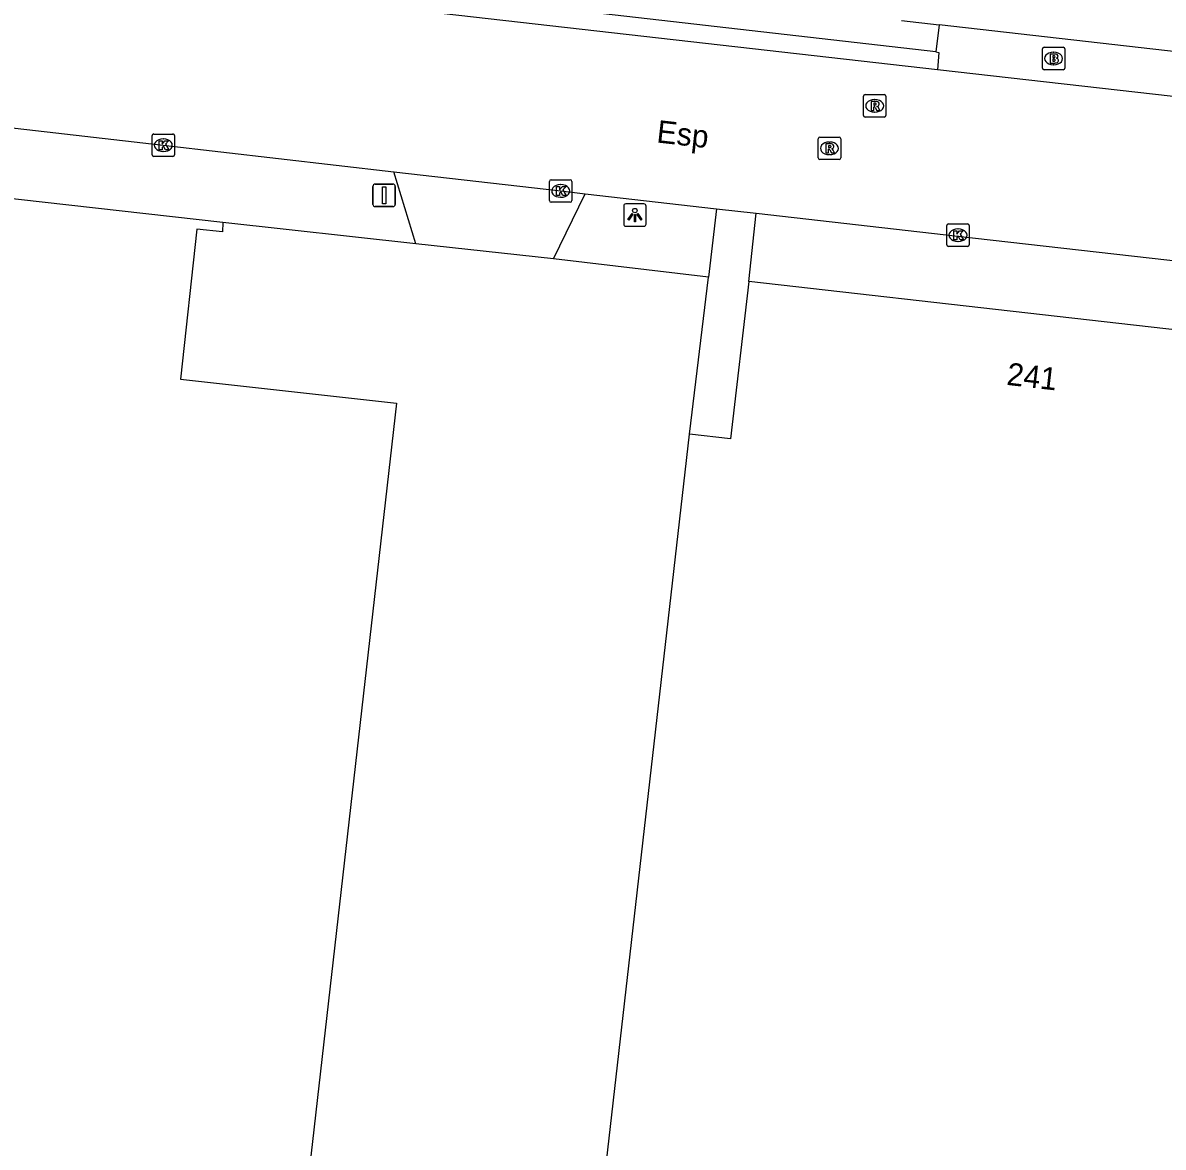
# Model space of a CAD drawing. Extents: x 161389 to 162585, y 388479 to 389761.
# Drawn here: x 162382.4 to 162433.2, y 388747.2 to 388797.2 of the extents above; entities that cross this region are included whole.
import ezdxf

# ---------------------------------------------------------------- set-up
doc = ezdxf.new("R2010")
doc.units = 0
for name, color, linetype in [('IMGEO_Afsluitpaal', 7, 'Continuous'), ('IMGEO_Brandkraan', 7, 'Continuous'), ('IMGEO_Groenvoorziening', 7, 'Continuous'), ('IMGEO_Haag', 7, 'Continuous'), ('IMGEO_Kolk', 7, 'Continuous'), ('IMGEO_Lichtpunt', 7, 'Continuous'), ('IMGEO_Openbare_ruimte_label', 7, 'Continuous'), ('IMGEO_Pand', 7, 'Continuous'), ('IMGEO_Pand_nummerreeks', 7, 'Continuous'), ('IMGEO_Rijbaan_lokaal_gesloten', 7, 'Continuous'), ('IMGEO_Rioolput', 7, 'Continuous'), ('IMGEO_Voetpad_open', 7, 'Continuous')]:
    doc.layers.add(name, color=color, linetype=linetype)

msp = doc.modelspace()

# ---------------------------------------------------------------- linework, layer by layer
at = {"layer": 'IMGEO_Afsluitpaal'}
for p, q in [((162398.007, 388789.155), (162398.007, 388789.955)), ((162398.007, 388789.955), (162398.007, 388789.155)), ((162398.107, 388790.055), (162398.897, 388790.055)), ((162398.897, 388790.055), (162398.107, 388790.055)), ((162398.997, 388789.955), (162398.997, 388789.155)), ((162398.997, 388789.155), (162398.997, 388789.955)), ((162398.897, 388789.055), (162398.107, 388789.055)), ((162398.107, 388789.055), (162398.897, 388789.055))]:
    msp.add_line(p, q, dxfattribs=at)
msp.add_lwpolyline([(162398.427, 388789.93), (162398.577, 388789.93), (162398.577, 388789.18), (162398.427, 388789.18), (162398.427, 388789.93)], dxfattribs=at)
for centre, start, end in [((162398.107, 388789.955), 90, 180), ((162398.107, 388789.955), 90, 180), ((162398.897, 388789.955), 0, 90), ((162398.897, 388789.955), 360, 90), ((162398.107, 388789.155), 180, 270), ((162398.107, 388789.155), 180, 270), ((162398.897, 388789.155), 270, 0), ((162398.897, 388789.155), 270, 0)]:
    msp.add_arc(centre, 0.1, start, end, dxfattribs=at)
at = {"layer": 'IMGEO_Brandkraan'}
for p, q in [((162427.808, 388795.222), (162427.808, 388796.074)), ((162427.883, 388796.148), (162428.735, 388796.148)), ((162428.296, 388795.928), (162428.321, 388795.928)), ((162428.809, 388796.074), (162428.809, 388795.222)), ((162428.319, 388795.368), (162428.294, 388795.368)), ((162428.735, 388795.148), (162427.883, 388795.148))]:
    msp.add_line(p, q, dxfattribs=at)
for points in [[(162427.808, 388795.222), (162427.808, 388796.074)], [(162427.883, 388796.148), (162428.735, 388796.148)], [(162428.156, 388795.848), (162428.156, 388795.448), (162428.369, 388795.448)], [(162428.387, 388795.848), (162428.156, 388795.848)], [(162428.809, 388796.074), (162428.809, 388795.222)], [(162428.335, 388795.767), (162428.281, 388795.767), (162428.281, 388795.691)], [(162428.281, 388795.691), (162428.334, 388795.691)], [(162428.343, 388795.615), (162428.281, 388795.615), (162428.281, 388795.534)], [(162428.281, 388795.534), (162428.343, 388795.534)], [(162428.735, 388795.148), (162427.883, 388795.148)]]:
    msp.add_lwpolyline(points, dxfattribs=at)
for centre, radius, start, end in [((162427.885, 388796.072), 0.0765, 91.552, 178.448), ((162427.885, 388796.072), 0.0765, 91.552, 178.448), ((162428.391, 388795.703), 0.145, 59.4692, 91.5367), ((162428.416, 388795.75), 0.0922, 285.5137, 58.1501), ((162428.733, 388796.072), 0.0765, 1.552, 88.448), ((162428.733, 388796.072), 0.0765, 1.552, 88.448), ((162428.336, 388795.729), 0.0379, 267.8285, 90.9355), ((162428.344, 388795.574), 0.0404, 269.8759, 90.5077), ((162428.375, 388795.699), 0.251, 268.6676, 293.5347), ((162428.421, 388795.558), 0.105, 301.3115, 78.989), ((162427.885, 388795.224), 0.0765, 181.552, 268.448), ((162427.885, 388795.224), 0.0765, 181.552, 268.448), ((162428.733, 388795.224), 0.0765, 271.552, 358.448), ((162428.733, 388795.224), 0.0765, 271.552, 358.448)]:
    msp.add_arc(centre, radius, start, end, dxfattribs=at)
for centre, major_axis, ratio, start_param, end_param in [((162428.295, 388795.648), (-0.387, 0.002), 0.722429, 4.712389, 7.853982), ((162428.32, 388795.648), (-0.39, 0.002), 0.717154, 1.570796, 4.712389)]:
    msp.add_ellipse(centre, major_axis=major_axis, ratio=ratio, start_param=start_param, end_param=end_param, dxfattribs=at)
at = {"layer": 'IMGEO_Groenvoorziening'}
msp.add_lwpolyline([(162399.91, 388787.404), (162391.318, 388788.343)], dxfattribs=at)
at = {"layer": 'IMGEO_Haag'}
msp.add_lwpolyline([(162412.94, 388785.911), (162406.049, 388786.722)], dxfattribs=at)
at = {"layer": 'IMGEO_Kolk'}
for p, q in [((162388.247, 388792.287), (162389.099, 388792.287)), ((162388.172, 388791.361), (162388.172, 388792.213)), ((162388.66, 388792.067), (162388.685, 388792.067)), ((162389.173, 388792.213), (162389.173, 388791.361)), ((162389.099, 388791.287), (162388.247, 388791.287)), ((162388.683, 388791.507), (162388.658, 388791.507)), ((162405.939, 388790.252), (162406.791, 388790.252)), ((162405.864, 388789.326), (162405.864, 388790.178)), ((162406.352, 388790.032), (162406.377, 388790.032)), ((162406.865, 388790.178), (162406.865, 388789.326)), ((162406.791, 388789.252), (162405.939, 388789.252)), ((162406.375, 388789.472), (162406.35, 388789.472)), ((162423.552, 388787.356), (162423.552, 388788.208)), ((162423.627, 388788.282), (162424.479, 388788.282)), ((162424.553, 388788.208), (162424.553, 388787.356)), ((162424.04, 388788.062), (162424.065, 388788.062)), ((162424.479, 388787.282), (162423.627, 388787.282)), ((162424.063, 388787.502), (162424.038, 388787.502))]:
    msp.add_line(p, q, dxfattribs=at)
for points in [[(162388.247, 388792.287), (162389.099, 388792.287)], [(162388.172, 388791.361), (162388.172, 388792.213)], [(162388.493, 388791.987), (162388.616, 388791.987), (162388.616, 388791.836), (162388.746, 388791.987), (162388.91, 388791.987), (162388.764, 388791.836), (162388.917, 388791.587), (162388.765, 388791.587), (162388.68, 388791.751), (162388.616, 388791.684), (162388.616, 388791.587), (162388.493, 388791.587), (162388.493, 388791.987)], [(162389.173, 388792.213), (162389.173, 388791.361)], [(162389.099, 388791.287), (162388.247, 388791.287)], [(162405.939, 388790.252), (162406.791, 388790.252)], [(162405.864, 388789.326), (162405.864, 388790.178)], [(162406.185, 388789.952), (162406.308, 388789.952), (162406.308, 388789.801), (162406.438, 388789.952), (162406.602, 388789.952), (162406.456, 388789.801), (162406.609, 388789.552), (162406.457, 388789.552), (162406.372, 388789.716), (162406.308, 388789.649), (162406.308, 388789.552), (162406.185, 388789.552), (162406.185, 388789.952)], [(162406.865, 388790.178), (162406.865, 388789.326)], [(162406.791, 388789.252), (162405.939, 388789.252)], [(162423.552, 388787.356), (162423.552, 388788.208)], [(162423.627, 388788.282), (162424.479, 388788.282)], [(162424.553, 388788.208), (162424.553, 388787.356)], [(162423.873, 388787.982), (162423.996, 388787.982), (162423.996, 388787.831), (162424.126, 388787.982), (162424.29, 388787.982), (162424.144, 388787.831), (162424.297, 388787.582), (162424.145, 388787.582), (162424.06, 388787.746), (162423.996, 388787.679), (162423.996, 388787.582), (162423.873, 388787.582), (162423.873, 388787.982)], [(162424.479, 388787.282), (162423.627, 388787.282)]]:
    msp.add_lwpolyline(points, dxfattribs=at)
for centre, start, end in [((162388.249, 388792.211), 91.552, 178.448), ((162388.249, 388792.211), 91.552, 178.448), ((162389.097, 388792.211), 1.552, 88.448), ((162389.097, 388792.211), 1.552, 88.448), ((162388.249, 388791.363), 181.552, 268.448), ((162388.249, 388791.363), 181.552, 268.448), ((162389.097, 388791.363), 271.552, 358.448), ((162389.097, 388791.363), 271.552, 358.448), ((162405.941, 388790.176), 91.552, 178.448), ((162405.941, 388790.176), 91.552, 178.448), ((162406.789, 388790.176), 1.552, 88.448), ((162406.789, 388790.176), 1.552, 88.448), ((162405.941, 388789.328), 181.552, 268.448), ((162405.941, 388789.328), 181.552, 268.448), ((162406.789, 388789.328), 271.552, 358.448), ((162406.789, 388789.328), 271.552, 358.448), ((162423.629, 388788.206), 91.552, 178.448), ((162423.629, 388788.206), 91.552, 178.448), ((162424.477, 388788.206), 1.552, 88.448), ((162424.477, 388788.206), 1.552, 88.448), ((162423.629, 388787.358), 181.552, 268.448), ((162423.629, 388787.358), 181.552, 268.448), ((162424.477, 388787.358), 271.552, 358.448), ((162424.477, 388787.358), 271.552, 358.448)]:
    msp.add_arc(centre, 0.0765, start, end, dxfattribs=at)
for centre, major_axis, ratio, start_param, end_param in [((162388.659, 388791.787), (-0.387, 0.002), 0.722429, 4.712389, 7.853982), ((162388.684, 388791.787), (-0.39, 0.002), 0.717154, 1.570796, 4.712389), ((162406.351, 388789.752), (-0.387, 0.002), 0.722429, 4.712389, 7.853982), ((162406.376, 388789.752), (-0.39, 0.002), 0.717154, 1.570796, 4.712389), ((162424.039, 388787.782), (-0.387, 0.002), 0.722429, 4.712389, 7.853982), ((162424.064, 388787.782), (-0.39, 0.002), 0.717154, 1.570796, 4.712389)]:
    msp.add_ellipse(centre, major_axis=major_axis, ratio=ratio, start_param=start_param, end_param=end_param, dxfattribs=at)
at = {"layer": 'IMGEO_Lichtpunt'}
for p, q in [((162409.169, 388789.08), (162409.169, 388788.273)), ((162409.169, 388789.08), (162409.169, 388788.273)), ((162410.071, 388789.175), (162409.263, 388789.175)), ((162410.071, 388789.175), (162409.263, 388789.175)), ((162410.165, 388788.273), (162410.165, 388789.08)), ((162410.165, 388788.273), (162410.165, 388789.08)), ((162409.263, 388788.179), (162410.071, 388788.179)), ((162409.263, 388788.179), (162410.071, 388788.179))]:
    msp.add_line(p, q, dxfattribs=at)
for points in [[(162409.543, 388788.744), (162409.582, 388788.716), (162409.394, 388788.454), (162409.356, 388788.481), (162409.543, 388788.744)], [(162409.755, 388788.716), (162409.793, 388788.743), (162409.98, 388788.481), (162409.941, 388788.453), (162409.755, 388788.716)], [(162409.645, 388788.696), (162409.692, 388788.696), (162409.692, 388788.374), (162409.645, 388788.374), (162409.645, 388788.696)]]:
    msp.add_lwpolyline(points, dxfattribs=at)
msp.add_circle((162409.668, 388788.878), 0.0994, dxfattribs=at)
for centre, start, end in [((162409.263, 388789.08), 90, 180), ((162409.263, 388789.08), 90, 180), ((162410.071, 388789.08), 0, 90), ((162410.071, 388789.08), 0, 90), ((162409.263, 388788.273), 180, 270), ((162409.263, 388788.273), 180, 270), ((162410.071, 388788.273), 270, 0), ((162410.071, 388788.273), 270, 360)]:
    msp.add_arc(centre, 0.0946, start, end, dxfattribs=at)
at = {"layer": 'IMGEO_Pand'}
for points in [[(162391.318, 388788.343), (162371.926, 388790.534), (162364.027, 388763.89), (162370.877, 388761.846), (162363.204, 388736.022)], [(162391.318, 388788.343), (162391.311, 388787.935), (162390.162, 388788.053), (162389.444, 388781.366), (162399.06, 388780.298), (162393.628, 388732.565), (162363.204, 388736.022)], [(162414.734, 388785.722), (162413.925, 388778.721), (162412.095, 388778.923)], [(162440.896, 388782.752), (162414.734, 388785.722)], [(162435.751, 388727.776), (162406.633, 388731.063), (162412.095, 388778.923)]]:
    msp.add_lwpolyline(points, dxfattribs=at)
at = {"layer": 'IMGEO_Rijbaan_lokaal_gesloten'}
for points in [[(162423.146, 388795.15), (162382.484, 388799.768)], [(162434.425, 388793.87), (162423.146, 388795.15)], [(162365.122, 388794.512), (162371.594, 388793.742), (162388.673, 388791.789), (162398.932, 388790.608)], [(162398.932, 388790.608), (162406.366, 388789.753), (162407.449, 388789.629)], [(162407.449, 388789.629), (162413.308, 388788.96)], [(162413.308, 388788.96), (162415.064, 388788.76)], [(162415.064, 388788.76), (162424.047, 388787.734), (162441.217, 388785.796)]]:
    msp.add_lwpolyline(points, dxfattribs=at)
at = {"layer": 'IMGEO_Rioolput'}
for p, q in [((162419.843, 388793.114), (162419.843, 388793.966)), ((162419.918, 388794.04), (162420.77, 388794.04)), ((162420.331, 388793.82), (162420.356, 388793.82)), ((162420.844, 388793.966), (162420.844, 388793.114)), ((162420.77, 388793.04), (162419.918, 388793.04)), ((162420.354, 388793.26), (162420.329, 388793.26)), ((162417.829, 388791.222), (162417.829, 388792.074)), ((162417.904, 388792.148), (162418.756, 388792.148)), ((162418.317, 388791.928), (162418.342, 388791.928)), ((162418.83, 388792.074), (162418.83, 388791.222)), ((162418.34, 388791.368), (162418.315, 388791.368)), ((162418.756, 388791.148), (162417.904, 388791.148))]:
    msp.add_line(p, q, dxfattribs=at)
for points in [[(162419.843, 388793.114), (162419.843, 388793.966)], [(162419.918, 388794.04), (162420.77, 388794.04)], [(162420.844, 388793.966), (162420.844, 388793.114)], [(162420.432, 388793.738), (162420.18, 388793.74), (162420.18, 388793.34)], [(162420.18, 388793.34), (162420.304, 388793.34), (162420.304, 388793.502), (162420.315, 388793.502)], [(162420.358, 388793.659), (162420.304, 388793.659), (162420.304, 388793.578)], [(162420.304, 388793.578), (162420.356, 388793.578)], [(162420.362, 388793.473), (162420.433, 388793.34), (162420.573, 388793.34), (162420.508, 388793.466)], [(162420.77, 388793.04), (162419.918, 388793.04)], [(162417.829, 388791.222), (162417.829, 388792.074)], [(162417.904, 388792.148), (162418.756, 388792.148)], [(162418.418, 388791.846), (162418.166, 388791.848), (162418.166, 388791.448)], [(162418.344, 388791.767), (162418.29, 388791.767), (162418.29, 388791.686)], [(162418.83, 388792.074), (162418.83, 388791.222)], [(162418.166, 388791.448), (162418.29, 388791.448), (162418.29, 388791.61), (162418.301, 388791.61)], [(162418.29, 388791.686), (162418.342, 388791.686)], [(162418.348, 388791.581), (162418.419, 388791.448), (162418.559, 388791.448), (162418.494, 388791.574)], [(162418.756, 388791.148), (162417.904, 388791.148)]]:
    msp.add_lwpolyline(points, dxfattribs=at)
for centre, radius, start, end in [((162419.92, 388793.964), 0.0765, 91.552, 178.448), ((162419.92, 388793.964), 0.0765, 91.552, 178.448), ((162420.768, 388793.964), 0.0765, 1.552, 88.448), ((162420.768, 388793.964), 0.0765, 1.552, 88.448), ((162420.314, 388793.449), 0.0533, 26.0293, 88.6989), ((162420.34, 388793.767), 0.19, 274.7715, 282.9687), ((162420.364, 388793.563), 0.0964, 77.0061, 93.1865), ((162420.378, 388793.62), 0.0378, 276.6634, 79.6772), ((162420.431, 388793.628), 0.109, 350.3612, 89.416), ((162420.429, 388793.628), 0.112, 277.5842, 350.9817), ((162420.413, 388793.413), 0.108, 29.5134, 73.7905), ((162419.92, 388793.116), 0.0765, 181.552, 268.448), ((162419.92, 388793.116), 0.0765, 181.552, 268.448), ((162420.768, 388793.116), 0.0765, 271.552, 358.448), ((162420.768, 388793.116), 0.0765, 271.552, 358.448), ((162417.906, 388792.072), 0.0765, 91.552, 178.448), ((162417.906, 388792.072), 0.0765, 91.552, 178.448), ((162418.35, 388791.671), 0.0964, 77.0061, 93.1865), ((162418.364, 388791.728), 0.0378, 276.6634, 79.6772), ((162418.417, 388791.736), 0.109, 350.3612, 89.416), ((162418.754, 388792.072), 0.0765, 1.552, 88.448), ((162418.754, 388792.072), 0.0765, 1.552, 88.448), ((162418.3, 388791.557), 0.0533, 26.0293, 88.6989), ((162418.326, 388791.875), 0.19, 274.7715, 282.9687), ((162418.415, 388791.736), 0.112, 277.5842, 350.9817), ((162418.399, 388791.521), 0.108, 29.5134, 73.7905), ((162417.906, 388791.224), 0.0765, 181.552, 268.448), ((162417.906, 388791.224), 0.0765, 181.552, 268.448), ((162418.754, 388791.224), 0.0765, 271.552, 358.448), ((162418.754, 388791.224), 0.0765, 271.552, 358.448)]:
    msp.add_arc(centre, radius, start, end, dxfattribs=at)
for centre, major_axis, ratio, start_param, end_param in [((162420.33, 388793.54), (-0.387, 0.002), 0.722429, 4.712389, 7.853982), ((162420.355, 388793.54), (-0.39, 0.002), 0.717154, 1.570796, 4.712389), ((162418.316, 388791.648), (-0.387, 0.002), 0.722429, 4.712389, 7.853982), ((162418.341, 388791.648), (-0.39, 0.002), 0.717154, 1.570796, 4.712389)]:
    msp.add_ellipse(centre, major_axis=major_axis, ratio=ratio, start_param=start_param, end_param=end_param, dxfattribs=at)
at = {"layer": 'IMGEO_Voetpad_open'}
for points in [[(162423.063, 388795.942), (162382.567, 388800.591)], [(162421.541, 388797.334), (162423.214, 388797.141)], [(162423.214, 388797.141), (162423.063, 388795.942)], [(162434.552, 388795.859), (162423.214, 388797.141)], [(162423.063, 388795.942), (162423.198, 388795.915), (162423.146, 388795.15)], [(162399.91, 388787.404), (162398.932, 388790.608)], [(162406.049, 388786.722), (162407.449, 388789.629)], [(162413.308, 388788.96), (162412.94, 388785.911)], [(162414.734, 388785.722), (162415.064, 388788.76)], [(162406.049, 388786.722), (162399.91, 388787.404)], [(162412.095, 388778.923), (162412.94, 388785.911)]]:
    msp.add_lwpolyline(points, dxfattribs=at)

# ---------------------------------------------------------------- texts
at = {"layer": 'IMGEO_Openbare_ruimte_label'}
msp.add_text('Esp', height=1, rotation=353.5143, dxfattribs=at).set_placement((162410.604, 388791.915))
at = {"layer": 'IMGEO_Pand_nummerreeks'}
msp.add_text('241', height=1, rotation=353.5256, dxfattribs=at).set_placement((162426.188, 388781.121))

doc.saveas('drawing.dxf')
